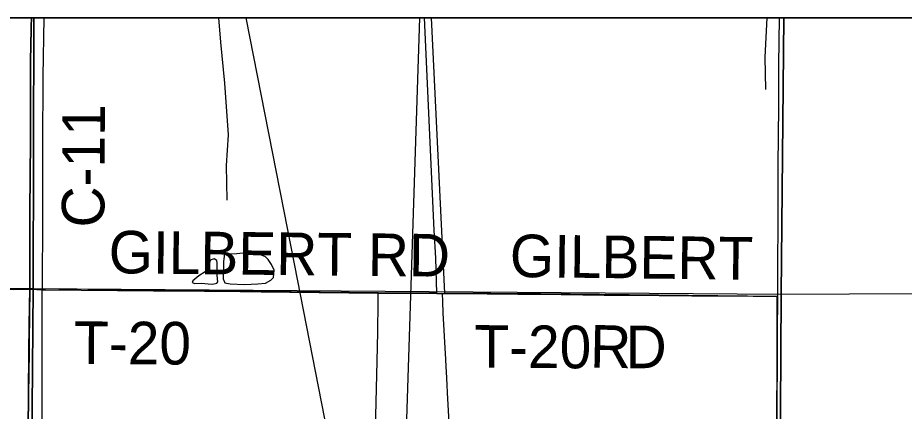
# Model space of a CAD drawing. Extents: x 0 to 34, y 0 to 22.
# Drawn here: x 3.136 to 4.321, y 20.375 to 20.9 of the extents above; entities that cross this region are included whole.
import ezdxf

# ---------------------------------------------------------------- set-up
doc = ezdxf.new("R2010")
doc.units = 0
for name, color, linetype in [('Default', 7, 'Continuous'), ('GM_X_City_Street', 7, 'Continuous'), ('GM_X_County_Road', 7, 'Continuous'), ('GM_X_County_Road_Text', 7, 'Continuous'), ('GM_X_Minor_Lake', 7, 'Continuous'), ('GM_X_Minor_River', 7, 'Continuous'), ('GM_X_Rail_Line', 7, 'Continuous'), ('GM_X_Section', 7, 'Continuous'), ('GM_X_State_Route', 7, 'Continuous'), ('GM_X_Township_Road', 7, 'Continuous'), ('GM_X_Township_Road_Text', 7, 'Continuous'), ('SH_Cut_Line', 7, 'Continuous'), ('SH_Data', 7, 'Continuous')]:
    doc.layers.add(name, color=color, linetype=linetype)

msp = doc.modelspace()

# ---------------------------------------------------------------- linework, layer by layer
at = {"layer": 'Default'}
for points in [[(3.1503, 20.3518), (3.1509, 20.3978), (3.1515, 20.4544), (3.1517, 20.4892), (3.1521, 20.5147), (3.1525, 20.5382), (3.1525, 20.5565), (3.1527, 20.605), (3.1528, 20.6379), (3.1531, 20.6933), (3.1535, 20.7312), (3.1537, 20.8039), (3.1537, 20.8462), (3.1541, 20.8604), (3.1545, 20.8883), (3.1549, 20.9), (2.1, 20.9)], [(4.1507, 20.2775), (4.1512, 20.5281), (3.835, 20.5316), (3.8299, 20.5313), (3.7071, 20.5325), (3.6891, 20.9), (3.6795, 20.9), (3.6924, 20.6166), (3.6944, 20.5793), (3.6961, 20.5326), (3.6178, 20.5328), (3.1525, 20.5382), (3.1509, 20.3978), (3.1497, 20.2765)], [(7.1734, 20.9), (3.1549, 20.9), (3.1545, 20.8883), (3.1541, 20.8604), (3.1537, 20.8462), (3.1537, 20.8039), (3.1535, 20.7312), (3.1531, 20.6933), (3.1528, 20.6379), (3.1527, 20.605), (3.1525, 20.5565), (3.1525, 20.5382), (3.1521, 20.5147), (3.1517, 20.4892), (3.1515, 20.4544), (3.1509, 20.3978), (3.1503, 20.3518)]]:
    msp.add_lwpolyline(points, dxfattribs=at)
for points in [[(3.1581, 20.9), (2.1495, 20.9), (2.1468, 20.5444), (3.1572, 20.5385)], [(4.1599, 20.9), (3.1581, 20.9), (3.1572, 20.5385), (4.1565, 20.5312)], [(5.1619, 20.9), (4.1599, 20.9), (4.1565, 20.5312), (5.1605, 20.536)]]:
    msp.add_lwpolyline(points, close=True, dxfattribs=at)
at = {"layer": 'GM_X_City_Street'}
for points in [[(3.6183, 20.2765), (3.6173, 20.2792), (3.6167, 20.2808), (3.6161, 20.2829), (3.6154, 20.2854), (3.6149, 20.2892), (3.6148, 20.293), (3.6145, 20.3135), (3.6147, 20.3294), (3.6149, 20.3686), (3.6166, 20.4417), (3.6174, 20.4802), (3.6179, 20.5203), (3.618, 20.5322)], [(3.7168, 20.2798), (3.7164, 20.2875), (3.7156, 20.3048), (3.7134, 20.3488), (3.7125, 20.368), (3.7108, 20.3996), (3.7102, 20.4101), (3.7092, 20.4275), (3.7088, 20.4343), (3.7083, 20.4442), (3.7067, 20.4746), (3.7063, 20.4832), (3.705, 20.5055), (3.7045, 20.5214), (3.7041, 20.5319)]]:
    msp.add_lwpolyline(points, dxfattribs=at)
at = {"layer": 'GM_X_County_Road'}
for points in [[(3.1528, 20.5377), (3.1527, 20.5559), (3.1529, 20.6044), (3.153, 20.6374), (3.1533, 20.6927), (3.1537, 20.7306), (3.1539, 20.8034), (3.1539, 20.8457), (3.1543, 20.8598), (3.1548, 20.8878), (3.1551, 20.9)], [(3.1492, 20.2146), (3.1492, 20.2175), (3.1495, 20.2411), (3.1499, 20.276), (3.15, 20.3164), (3.1505, 20.3512), (3.1511, 20.3972), (3.1517, 20.4538), (3.1519, 20.4887), (3.1523, 20.5141), (3.1528, 20.5377)]]:
    msp.add_lwpolyline(points, dxfattribs=at)
at = {"layer": 'GM_X_Minor_Lake'}
for p, q in [((3.4029, 20.556), (3.403, 20.5727)), ((3.4113, 20.574), (3.4108, 20.5517))]:
    msp.add_line(p, q, dxfattribs=at)
for points in [[(3.4108, 20.5517), (3.4133, 20.5463), (3.4204, 20.545), (3.4394, 20.5438), (3.4572, 20.5449), (3.4674, 20.5457), (3.4747, 20.5497), (3.4782, 20.5535), (3.4792, 20.5629), (3.4756, 20.5706), (3.4712, 20.5775), (3.4675, 20.5807), (3.4567, 20.5855), (3.4415, 20.5862), (3.429, 20.585), (3.4203, 20.5845), (3.4127, 20.5854), (3.4113, 20.574)], [(3.403, 20.5727), (3.4027, 20.5758), (3.3989, 20.5781), (3.3936, 20.5764), (3.3915, 20.5669), (3.3868, 20.561), (3.3783, 20.5555), (3.3706, 20.5488), (3.3694, 20.5466), (3.3731, 20.5454), (3.3818, 20.5459), (3.3909, 20.5449), (3.3966, 20.5444), (3.4023, 20.5458), (3.4039, 20.5477), (3.4029, 20.556)]]:
    msp.add_lwpolyline(points, dxfattribs=at)
at = {"layer": 'GM_X_Minor_River'}
for points in [[(3.1715, 20.9), (3.1702, 20.8216), (3.1694, 20.729), (3.1695, 20.611), (3.1686, 20.5131), (3.1685, 20.3579), (3.1631, 20.3539), (3.1651, 20.2954), (3.1689, 20.1913), (3.1684, 20.1101), (3.1636, 20.04), (3.1658, 19.9899), (3.1637, 19.9209), (3.162, 19.8215)], [(3.4047, 20.9), (3.4076, 20.8675), (3.4127, 20.8127), (3.4178, 20.7435), (3.4149, 20.7026), (3.416, 20.6563)], [(4.1374, 20.9), (4.1346, 20.8473), (4.1354, 20.804)]]:
    msp.add_lwpolyline(points, dxfattribs=at)
at = {"layer": 'GM_X_Rail_Line'}
for points in [[(3.4414, 20.9), (3.5016, 20.5918), (3.7507, 19.321), (3.8733, 18.7042), (3.9207, 18.4339), (3.9385, 18.3568), (3.9629, 18.2975), (3.9974, 18.239), (4.1223, 18.078), (4.3281, 17.8226), (4.3689, 17.7633), (4.4066, 17.7097), (4.4454, 17.6387), (4.4793, 17.5709), (4.5132, 17.4611), (4.5342, 17.361), (4.5504, 17.2625), (4.562, 17.1188)], [(3.6732, 20.9), (3.6471, 20.09), (3.6471, 19.9081), (3.752, 19.3659), (3.9326, 18.4227), (3.949, 18.3555), (3.9754, 18.3001), (4.0116, 18.2329), (4.0712, 18.1586), (4.3307, 17.8397), (4.4282, 17.7343), (4.663, 17.5576), (4.8455, 17.4299), (4.9093, 17.3662)]]:
    msp.add_lwpolyline(points, dxfattribs=at)
at = {"layer": 'GM_X_Section'}
for points in [[(3.1572, 20.5385), (3.1487, 19.529), (2.1432, 19.5299), (2.1468, 20.5444)], [(4.1565, 20.5312), (4.1507, 19.5243), (3.1487, 19.529), (3.1572, 20.5385)], [(5.1605, 20.536), (5.1538, 19.525), (4.1507, 19.5243), (4.1565, 20.5312)]]:
    msp.add_lwpolyline(points, close=True, dxfattribs=at)
at = {"layer": 'GM_X_State_Route'}
for points in [[(2.1, 20.5438), (2.1112, 20.5438), (2.1485, 20.5438), (2.1765, 20.5436), (2.2806, 20.5431), (2.3474, 20.5429), (2.4764, 20.5419), (2.5836, 20.5412), (2.6629, 20.5405), (2.7111, 20.54), (2.7577, 20.5397), (2.8276, 20.5394), (2.9084, 20.5387), (2.9379, 20.5385), (3.0032, 20.538), (3.0871, 20.5376), (3.1306, 20.5373), (3.1528, 20.5377)], [(3.1528, 20.5377), (3.1523, 20.5141), (3.1519, 20.4887), (3.1517, 20.4538), (3.1511, 20.3972), (3.1505, 20.3512), (3.15, 20.3164), (3.1499, 20.276), (3.1495, 20.2411), (3.1492, 20.2175), (3.1492, 20.2146)]]:
    msp.add_lwpolyline(points, dxfattribs=at)
at = {"layer": 'GM_X_Township_Road'}
for p, q in [((3.6963, 20.532), (3.7041, 20.5319)), ((3.7041, 20.5319), (3.7073, 20.5319))]:
    msp.add_line(p, q, dxfattribs=at)
for points in [[(4.1519, 20.5279), (4.1518, 20.5829), (4.1522, 20.6132), (4.1523, 20.6399), (4.1523, 20.6741), (4.1525, 20.7009), (4.1529, 20.7443), (4.1531, 20.7794), (4.1533, 20.8373), (4.1542, 20.9)], [(3.1528, 20.5377), (3.1619, 20.5373), (3.169, 20.537), (3.1737, 20.5369), (3.2212, 20.5363), (3.3181, 20.5354), (3.3858, 20.5352), (3.4337, 20.5345), (3.4616, 20.5343), (3.5002, 20.5339), (3.618, 20.5322)], [(3.618, 20.5322), (3.6291, 20.5322), (3.6583, 20.5322), (3.6626, 20.5322), (3.6963, 20.532)], [(3.7073, 20.5319), (3.7226, 20.532), (3.8047, 20.531), (3.8625, 20.5305), (3.9201, 20.5299), (3.9499, 20.5298), (4.0369, 20.5289), (4.086, 20.5287), (4.1519, 20.5279)], [(4.151, 20.277), (4.1513, 20.2992), (4.1512, 20.3203), (4.1511, 20.3495), (4.1514, 20.478), (4.1519, 20.5279)]]:
    msp.add_lwpolyline(points, dxfattribs=at)
at = {"layer": 'SH_Cut_Line'}
msp.add_lwpolyline([(7.1734, 20.9), (2.1, 20.9), (2.1, 14.1)], dxfattribs=at)
at = {"layer": 'SH_Data'}
msp.add_line((2.1, 20.9), (8.9, 20.9), dxfattribs=at)

# ---------------------------------------------------------------- texts
at = {"layer": 'GM_X_County_Road_Text'}
msp.add_text('C-11', height=0.05682, rotation=89.6656, dxfattribs=at).set_placement((3.2521, 20.6199))
at = {"layer": 'GM_X_Township_Road_Text'}
for s, height, rotation, p in [('GILBERT RD', 0.05682, 359.4123, (3.2578, 20.559)), ('GILBERT', 0.05682, 359.3519, (3.7937, 20.554)), ('T-20', 0.05682, 359.6516, (3.2116, 20.438)), ('T-20', 0.05682, 359.6457, (3.7463, 20.433)), ('R', 0.0568, 358.8446, (3.9007, 20.4333)), ('D', 0.0568, 359.9664, (3.9486, 20.4323))]:
    msp.add_text(s, height=height, rotation=rotation, dxfattribs=at).set_placement(p)

doc.saveas('drawing.dxf')
